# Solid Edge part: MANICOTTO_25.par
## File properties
Subject: MANICOTTO_25
Author: Francesco
Template: Normal.par
Last saved by: f_grande
Revision: 6
Application: Solid Edge
Densità: 2712,000 kg/m^3
Precisione: 0,990
Tipo di contenuto documento: 0
Document Number: KR0131
Material: Alluminio, 1060
Stile della faccia: Alluminio
Stile di riempimento: ANSI38(Alluminio)
Stile virtuale: Alluminio lucidato
Coef. of Thermal Exp: 0.0
Thermal Conductivity: 221.0
Specific Heat: 920.0
Modulus of Elasticity: 68947570000.0
Poisson's Ratio: 0.33
Yield Stress: 27579028.0
Ultimate Stress: 68947570.0
Elongation: 0.0
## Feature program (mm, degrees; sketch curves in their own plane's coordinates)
sketch for "unnamed Protrusion 1" plane through (0, 0, 0) normal (0, -1, 0) x-axis (1, 0, 0)
  line (-13.0756, 31.4215) -> (25.1244, 31.4215)
  line (25.1244, 31.4215) -> (25.1244, 18.4215)
  line (25.1244, 18.4215) -> (24.1244, 18.4215)
  line (24.1244, 18.4215) -> (24.1244, -9.8785)
  line (24.1244, -9.8785) -> (7.9244, -9.8785)
  line (7.9244, -9.8785) -> (7.9244, -20.3785)
  line (7.9244, -20.3785) -> (-13.0756, -20.3785)
  line (-13.0756, -20.3785) -> (-13.0756, 31.4215)
  dimension (linear) = 7.9244
  dimension (linear) = 13.0756
  dimension (linear) = 25.1244
  dimension (linear) = 7.9244
extrude "unnamed Protrusion 1" add finite 130.1 along -normal
body pattern "unnamed BodyPattern 1"
pattern "unnamed Pattern 1"
chamfer "Smusso_1" setback 1
sketch for "unnamed Cutout 1" plane through (-13.0756, 0, -6.5285) normal (0, -1, 0) x-axis (1, 0, 0)
  line (0, 37.95) -> (6.5, 37.95)
  line (6.5, 37.95) -> (6.5, 37.45)
  line (6.5, 37.45) -> (-6.5, 37.45)
  line (-6.5, 37.45) -> (-6.5, 37.95)
  line (-6.5, 37.95) -> (0, 37.95)
  dimension (linear) = 6.5
extrude "unnamed Cutout 1" cut to key point along -normal
chamfer "Smusso_2" setback 0.5
chamfer "Smusso_3" setback 10.5
sketch for "Foro_1" plane through (-27.0756, 35.05, 31.4215) normal (0, 0, 1) x-axis (0, 1, 0)
  hole centre (79.85, 12.8) bore radius 3.5
hole "Foro_1" diameter 7 through
sketch for "unnamed Hole 1" plane through (-27.0756, 35.05, 31.4215) normal (0, 0, 1) x-axis (0, 1, 0)
  hole centre (79.85, -40.8) bore radius 3.5
hole "unnamed Hole 1" through
sketch for "unnamed Hole 2" plane through (-27.0756, 35.05, 31.4215) normal (0, 0, 1) x-axis (0, 1, 0)
  hole centre (-19.9, -40.8) bore radius 3.5
hole "unnamed Hole 2" through
sketch for "unnamed Hole 3" plane through (-27.0756, 35.05, 31.4215) normal (0, 0, 1) x-axis (0, 1, 0)
  hole centre (-19.9, 12.8) bore radius 3.5
hole "unnamed Hole 3" through
pattern "unnamed Pattern 2" of "Foro_1", "unnamed Hole 1", "unnamed Hole 2", "unnamed Hole 3"
sketch for "Foro_5" plane through (-13.0756, 0, -6.5285) normal (0, -1, 0) x-axis (1, 0, 0)
  hole centre (0, 11.55) bore radius 12.5
hole "Foro_5" diameter 25 through
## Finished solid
Body 1: solid body, 23 faces, 58 edges, 32 vertices.
  Faces by surface: plane 18, cylinder 5
  Edges by curve: line 48, circle 10
Bounding box of the edges (mm): 76.400 x 130.100 x 51.800, from (-51.2756, 0, -20.3785) to (25.1244, 130.1, 31.4215).
Cylindrical faces by radius (mm): R3.5 x4, R12.5 x1
Planar faces by outward normal: +x 2, +y 1, +z 3, -x 2, -y 1, -z 3, oblique 6
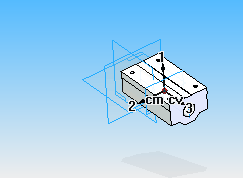
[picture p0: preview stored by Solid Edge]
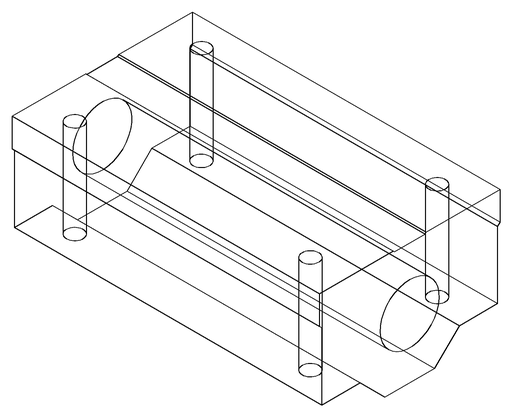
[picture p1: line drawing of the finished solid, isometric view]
